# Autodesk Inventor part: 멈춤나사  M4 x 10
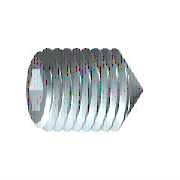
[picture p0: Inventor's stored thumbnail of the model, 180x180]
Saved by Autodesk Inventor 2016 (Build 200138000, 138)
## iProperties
Created: 2012-02
Part Number: 멈춤나사  M4 x 10
Material: 강철, 연강
Description: 6각 소켓 머리 없는 멈춤 나사
Document SubType Name: Modeling
Standard: KS B 1028
Designer: mduedu
Standards Organization: KS
Language: ko-KR
Size Designation: 원추점 M4x10
Categories: <MemberInstance><Categories><Category DisplayName="조임쇠" InternalName="e4da775c-781d-43d5-af7c-5136215cf5a6" Mnemonic="FSTN"><Category DisplayName="볼트" InternalN
Density: 7.86 g/cm^3
Mass: 0.792069 g
Surface Area: 1.48192 cm^2
Volume: 0.100772 cm^3
Appearance: 강철
Author: mduedu
IsCustomPart: 1
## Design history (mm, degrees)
sketch "스케치1"
  geometry: L1 (0, 0)-(6.833, 0); L2 (10, 1.155)-(10, 2); L3 (10, 2)-(0, 2); L4 (10, 1.155)-(7.5, 1.155); L5 (7.5, 1.155)-(6.833, 0); L6 (0, -0.4)-(0, 2.4) reference; L7 (0, 2)-(0, 0)
  constraints: 13 end point, 3 parallel, 1 collinear, 1 perpendicular, 1 point on line
  dimensions: "d0" = 2.5 distance of L2.start L4.end (= INTI); "d1" = 60 deg angle of L5 L1; "d2" = 4 diameter of L3 L1 (= NND); "d3" = 2.3094 diameter of L4 L1 (= 1.1547 x SW); "d5" = 10 distance from line of L2 L3.end (= NLG)
revolve "본체" sketch "스케치1" stored, may be unused: angle "d6" = 90 deg
sketch "스케치2"
  geometry: L1 (-0.577, 1)-(0.577, 1); L2 (0.577, 1)-(1.155, 0); L3 (1.155, 0)-(0.577, -1); L4 (0.577, -1)-(-0.577, -1); L5 (-0.577, -1)-(-1.155, 0); L6 (-1.155, 0)-(-0.577, 1); 3 further points
  constraints: 12 end point, 1 coincident, 1 horizontal, 13 other
extrude "슬롯" join sketch "스케치2" taper "d7" = 0 deg; stored distance "d21" = 10
workaxis "Work Axis1"
workplane "Work Plane1"
sketch "스케치4"
  geometry: L1 (-5, 0.2)-(-3.2, 2) reference; L2 (-5, -0.2)-(-3.2, -2) reference; L3 (-3.2, 2)-(-5.2, 0); L4 (-3.2, -2)-(-5.2, 0); 2 further points
  constraints: 4 end point, 2 collinear, 1 coincident
body "Solid1"
feature "스레드" dims "d12" = 10 (= NLG), "d13" = 0
chamfer "모따기1" distance "d8" = 1.8 (computed from NND, SPD, FAWI); stored, may be unused: angle "d9" = 45 deg (= FAWI), second distance "d34" = 1.8 (computed from NND, SPD, FAWI)
chamfer "모따기2" distance "d10" = 0.42941 (= -0.5 x GD1 + 0.5 x NND); stored, may be unused: angle "d11" = 45 deg (= FAWI), second distance "d35" = 0.42941 (= -0.5 x GD1 + 0.5 x NND)
other parameters: "NND" = 4 [user parameter; used in 5 equation terms], "NLG" = 10 [user parameter; used in 2 equation terms], "INTI" = 2.5 [user parameter; used in 1 equation term], "FAWI" = 45 deg [user parameter; used in 4 equation terms], "SW" = 2 [user parameter; used in 2 equation terms], "GD1" = 3.14117 (= THREADDIA - 1.2269 x PTC) [user parameter; used in 2 equation terms], "d4" = 0, "FAWI1" = 45 deg [user parameter], "SPD" = 0.4 [user parameter; used in 2 equation terms], "d36" = 0, "d37" = 0, "GUL" = 0.42941 (= 0.61345 x PTC) [user parameter], "TPU" = 14.28571 (computed from PTC) [user parameter], "TOA" = 30 deg [user parameter], "THREADDIA" = 4 [user parameter; used in 1 equation term], "PTC" = 0.7 [user parameter; used in 4 equation terms], "GAL" = 0.42941 (= 0.61345 x PTC) [user parameter], "E0" = 2.31 (= 1.155 x SW) [user parameter]
